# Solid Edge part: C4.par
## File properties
Author: edge
Template: Jis Part.par
Last saved by: edge
Revision: 3
Application: Solid Edge
Username: edge
文書内容のタイプ: 0
Accuracy: 0.990
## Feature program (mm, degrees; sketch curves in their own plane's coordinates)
sketch for "unnamed Protrusion 1" plane through (0, 0, 0) normal (0, 0, 1) x-axis (1, 0, 0)
  circle centre (0, 0) radius 30
extrude "unnamed Protrusion 1" add finite 40 along +normal
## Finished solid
Body 1: solid body, 3 faces, 2 edges, 0 vertices.
  Faces by surface: plane 2, cylinder 1
  Edges by curve: circle 2
Bounding box of the edges (mm): 60.000 x 60.000 x 40.000, from (-30, -30, 0) to (30, 30, 40).
Cylindrical faces by radius (mm): R30 x1
Planar faces by outward normal: +z 1, -z 1
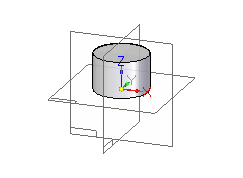
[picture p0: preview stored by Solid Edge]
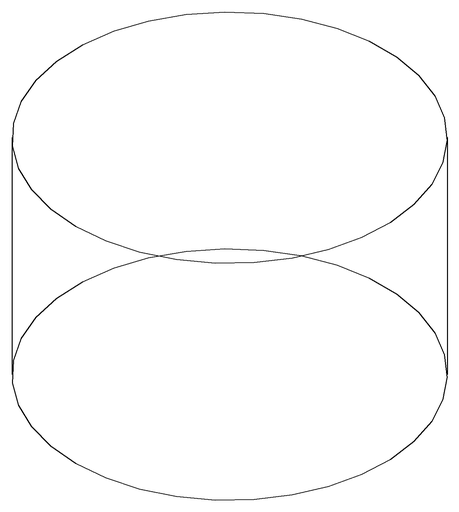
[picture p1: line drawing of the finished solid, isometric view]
